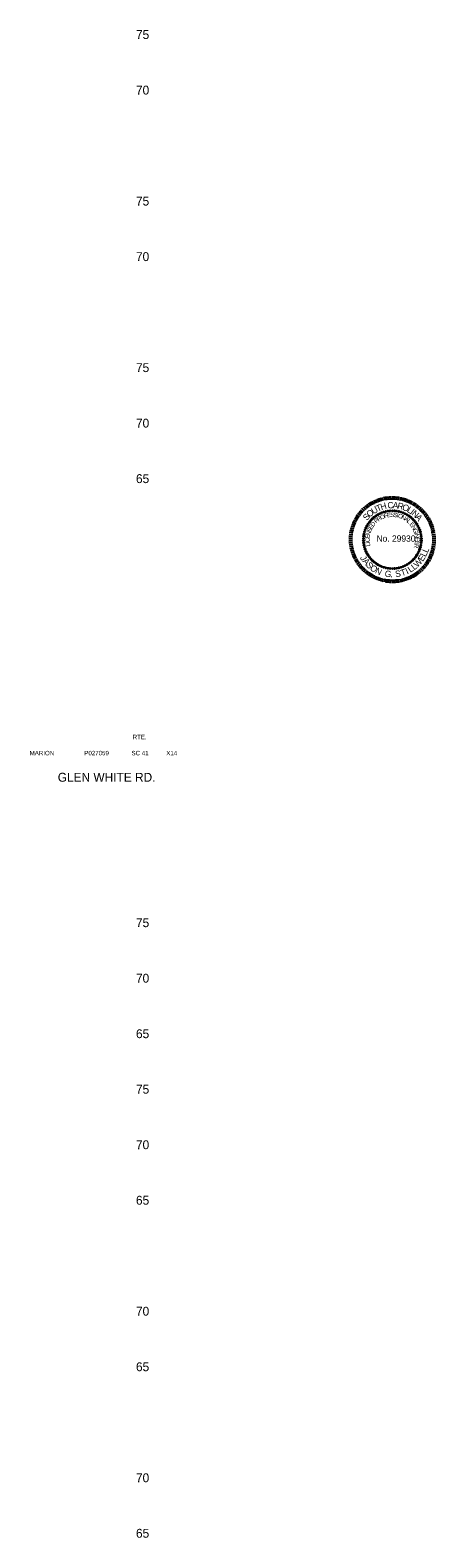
# Model space of a CAD drawing. Extents: x 1001 to 1184, y 1001 to 1562.
# Drawn here: x 1147.4 to 1183.9, y 1145 to 1280.8 of the extents above; entities that cross this region are included whole.
import ezdxf

# ---------------------------------------------------------------- set-up
doc = ezdxf.new("R2010")
doc.units = 0
for name, color, linetype in [('RD_HC_Cl', 7, 'Continuous'), ('RD_SHT_TX', 7, 'Continuous'), ('RD_TX_PEShield', 7, 'Continuous'), ('RD_XS_TX_Elev_EX', 7, 'Continuous')]:
    doc.layers.add(name, color=color, linetype=linetype)

# ---------------------------------------------------------------- blocks, each defined once
blk = doc.blocks.new('STILLWELL')
at = {"layer": 'RD_TX_PEShield'}
for p, q in [((-23.8, 25.9), (-26, 28.4)), ((-22.5, 27), (-24.5, 29.6)), ((-21.1, 28.1), (-23, 30.7)), ((-19.7, 29.1), (-21.5, 31.8)), ((-18.2, 30), (-19.9, 32.8)), ((-16.7, 30.8), (-18.2, 33.7)), ((-15.1, 31.6), (-16.5, 34.6)), ((-13.6, 32.3), (-14.8, 35.3)), ((-11.9, 32.9), (-13, 36)), ((-10.3, 33.4), (-11.2, 36.6)), ((-8.6, 33.9), (-9.4, 37.1)), ((-6.9, 34.3), (-7.5, 37.5)), ((-5.2, 34.6), (-5.7, 37.8)), ((-3.5, 34.8), (-3.8, 38)), ((-1.8, 34.9), (-1.9, 38.2)), ((0, 34.9), (0, 38.2)), ((1.7, 34.9), (1.9, 38.2)), ((3.4, 34.8), (3.7, 38)), ((5.2, 34.6), (5.6, 37.8)), ((6.9, 34.3), (7.5, 37.5)), ((8.6, 33.9), (9.3, 37.1)), ((10.2, 33.4), (11.2, 36.6)), ((11.9, 32.9), (13, 36)), ((13.5, 32.3), (14.7, 35.3)), ((15.1, 31.6), (16.5, 34.6)), ((16.6, 30.8), (18.2, 33.7)), ((18.2, 30), (19.8, 32.8)), ((19.6, 29.1), (21.4, 31.8)), ((21.1, 28.1), (23, 30.7)), ((22.4, 27), (24.5, 29.6)), ((23.8, 25.9), (25.9, 28.4)), ((-32.9, 13.4), (-35.9, 14.7)), ((-32.2, 15), (-35.1, 16.4)), ((-31.4, 16.5), (-34.2, 18.1)), ((-30.5, 18), (-33.3, 19.7)), ((-29.5, 19.4), (-32.2, 21.3)), ((-28.5, 20.9), (-31.1, 22.8)), ((-27.4, 22.2), (-29.9, 24.3)), ((-26.3, 23.5), (-28.7, 25.7)), ((-25.1, 24.7), (-27.4, 27.1)), ((25, 24.7), (27.3, 27.1)), ((26.2, 23.5), (28.6, 25.7)), ((27.4, 22.2), (29.9, 24.3)), ((28.5, 20.9), (31.1, 22.8)), ((29.5, 19.4), (32.2, 21.3)), ((30.4, 18), (33.2, 19.7)), ((31.3, 16.5), (34.2, 18.1)), ((32.1, 15), (35.1, 16.4)), ((32.9, 13.4), (35.9, 14.7)), ((-35.9, -0.1), (-39.2, 0)), ((-35.8, 1.7), (-39.1, 1.9)), ((-35.6, 3.4), (-38.9, 3.8)), ((-35.4, 5.1), (-38.6, 5.7)), ((-35.1, 6.8), (-38.2, 7.5)), ((-34.6, 8.5), (-37.8, 9.4)), ((-34.1, 10.2), (-37.2, 11.2)), ((-33.6, 11.8), (-36.6, 12.9)), ((33.5, 11.8), (36.6, 12.9)), ((34.1, 10.2), (37.2, 11.2)), ((34.6, 8.5), (37.7, 9.4)), ((35, 6.8), (38.2, 7.5)), ((35.3, 5.1), (38.5, 5.7)), ((35.6, 3.4), (38.8, 3.8)), ((35.7, 1.7), (39, 1.9)), ((35.8, -0.1), (39.1, 0)), ((-35.9, -1.8), (-39.2, -1.9)), ((-35.8, -3.5), (-39.1, -3.8)), ((-35.6, -5.3), (-38.9, -5.6)), ((-35.4, -7), (-38.6, -7.5)), ((-35.1, -8.7), (-38.2, -9.4)), ((-34.6, -10.4), (-37.8, -11.2)), ((-34.1, -12), (-37.2, -13)), ((34.1, -12), (37.2, -13)), ((34.6, -10.4), (37.7, -11.2)), ((35, -8.7), (38.2, -9.4)), ((35.3, -7), (38.5, -7.5)), ((35.6, -5.3), (38.8, -5.6)), ((35.7, -3.5), (39, -3.8)), ((35.8, -1.8), (39.1, -1.9)), ((-33.6, -13.6), (-36.6, -14.8)), ((-32.9, -15.3), (-35.9, -16.6)), ((-32.2, -16.8), (-35.1, -18.3)), ((-31.4, -18.4), (-34.2, -19.9)), ((-30.5, -19.9), (-33.3, -21.6)), ((-29.5, -21.3), (-32.2, -23.2)), ((-28.5, -22.7), (-31.1, -24.7)), ((-27.4, -24.1), (-29.9, -26.2)), ((-26.3, -25.4), (-28.7, -27.6)), ((-25.1, -26.6), (-27.4, -28.9)), ((25, -26.6), (27.3, -28.9)), ((26.2, -25.4), (28.6, -27.6)), ((27.4, -24.1), (29.9, -26.2)), ((28.5, -22.7), (31.1, -24.7)), ((29.5, -21.3), (32.2, -23.2)), ((30.4, -19.9), (33.2, -21.6)), ((31.3, -18.4), (34.2, -19.9)), ((32.1, -16.8), (35.1, -18.3)), ((32.9, -15.3), (35.9, -16.6)), ((33.5, -13.6), (36.6, -14.8)), ((-23.8, -27.8), (-26, -30.2)), ((-22.5, -28.9), (-24.5, -31.4)), ((-21.1, -29.9), (-23, -32.6)), ((-19.7, -30.9), (-21.5, -33.7)), ((-18.2, -31.8), (-19.9, -34.7)), ((-16.7, -32.7), (-18.2, -35.6)), ((-15.1, -33.5), (-16.5, -36.4)), ((-13.6, -34.1), (-14.8, -37.2)), ((-11.9, -34.8), (-13, -37.8)), ((-10.3, -35.3), (-11.2, -38.4)), ((-8.6, -35.8), (-9.4, -38.9)), ((-6.9, -36.1), (-7.5, -39.3)), ((-5.2, -36.4), (-5.7, -39.7)), ((-3.5, -36.6), (-3.8, -39.9)), ((-1.8, -36.8), (-1.9, -40)), ((0, -36.8), (0, -40.1)), ((1.7, -36.8), (1.9, -40)), ((3.4, -36.6), (3.7, -39.9)), ((5.2, -36.4), (5.6, -39.7)), ((6.9, -36.1), (7.5, -39.3)), ((8.6, -35.8), (9.3, -38.9)), ((10.2, -35.3), (11.2, -38.4)), ((11.9, -34.8), (13, -37.8)), ((13.5, -34.1), (14.7, -37.2)), ((15.1, -33.5), (16.5, -36.4)), ((16.6, -32.7), (18.2, -35.6)), ((18.2, -31.8), (19.8, -34.7)), ((19.6, -30.9), (21.4, -33.7)), ((21.1, -29.9), (23, -32.6)), ((22.4, -28.9), (24.5, -31.4)), ((23.8, -27.8), (25.9, -30.2))]:
    blk.add_line(p, q, dxfattribs=at)
for centre in [(-21.9, 13.2), (-20.7, 14.9), (-19.5, 16.4), (-18.1, 17.8), (-16.6, 19.2), (-15, 20.4), (-13.3, 21.5), (-11.6, 22.4), (-9.8, 23.2), (-7.9, 23.9), (-6, 24.4), (-4, 24.8), (-2, 25), (0, 25.1), (2, 25), (3.9, 24.8), (5.9, 24.4), (7.8, 23.9), (9.7, 23.2), (11.5, 22.4), (13.3, 21.5), (15, 20.4), (16.5, 19.2), (18, 17.8), (19.4, 16.4), (20.7, 14.9), (21.8, 13.2), (-26.1, 0.1), (-25.9, 2.1), (-25.6, 4), (-25.1, 6), (-24.5, 7.9), (-23.8, 9.7), (-22.9, 11.5), (22.9, 11.5), (23.7, 9.7), (24.5, 7.9), (25.1, 6), (25.5, 4), (25.8, 2.1), (26, 0.1), (-26.1, -1.9), (-25.9, -3.9), (-25.6, -5.9), (-25.1, -7.8), (-24.5, -9.7), (-23.8, -11.6), (-22.9, -13.4), (22.9, -13.4), (23.7, -11.6), (24.5, -9.7), (25.1, -7.8), (25.5, -5.9), (25.8, -3.9), (26, -1.9), (-21.9, -15.1), (-20.7, -16.7), (-19.5, -18.3), (-18.1, -19.7), (-16.6, -21), (-15, -22.2), (-13.3, -23.3), (-11.6, -24.3), (-9.8, -25.1), (-7.9, -25.8), (-6, -26.3), (-4, -26.7), (-2, -26.9), (0, -27), (2, -26.9), (3.9, -26.7), (5.9, -26.3), (7.8, -25.8), (9.7, -25.1), (11.5, -24.3), (13.3, -23.3), (15, -22.2), (16.5, -21), (18, -19.7), (19.4, -18.3), (20.7, -16.7), (21.8, -15.1)]:
    blk.add_circle(centre, 0.49, dxfattribs=at)
for s, height, rotation, p in [('U', 5.68, 32.2152, (-16.9, 21.8)), ('T', 5.68, 23.5044, (-13.2, 24.1)), ('H', 5.68, 16.1357, (-9.9, 25.6)), ('C', 5.68, 4.076, (-4.2, 27.1)), ('A', 5.68, 355.3651, (0.1, 27.4)), ('R', 5.68, 347.3188, (4.1, 27.1)), ('O', 5.68, 338.6079, (8.3, 26.2)), ('L', 5.68, 329.226, (12.6, 24.4)), ('S', 5.68, 49.6435, (-22.9, 15.8)), ('O', 5.68, 41.5972, (-20.4, 18.8)), ('D', 3.92, 52.5376, (-17.1, 10.3)), ('P', 3.92, 41.0022, (-14.5, 13.5)), ('R', 3.92, 33.3057, (-12.5, 15.3)), ('O', 3.92, 24.9735, (-10, 16.9)), ('F', 3.92, 15.9995, (-7.1, 18.3)), ('E', 3.92, 8.9511, (-4.7, 19)), ('S', 3.92, 1.2546, (-1.9, 19.4)), ('S', 3.92, 353.558, (0.8, 19.5)), ('I', 3.92, 345.8615, (3.5, 19.2)), ('O', 3.92, 342.6583, (4.7, 19)), ('N', 3.92, 333.6842, (7.7, 18)), ('A', 3.92, 325.3521, (10.4, 16.7)), ('L', 3.92, 317.6555, (12.6, 15.1)), ('E', 3.92, 308.0396, (15.1, 12.8)), ('I', 5.68, 322.5218, (15.5, 22.8)), ('N', 5.68, 319.1729, (16.8, 21.8)), ('A', 5.68, 310.4621, (20.1, 19)), ('C', 3.92, 92.2915, (-20.4, -3.2)), ('E', 3.92, 83.9594, (-20.5, -0.2)), ('N', 3.92, 76.2628, (-20.2, 2.5)), ('S', 3.92, 67.9307, (-19.5, 5.4)), ('E', 3.92, 60.2341, (-18.5, 7.9)), ('N', 3.92, 300.343, (16.8, 10.6)), ('G', 3.92, 292.0109, (18.3, 8.1)), ('I', 3.92, 283.0368, (19.5, 5.1)), ('N', 3.92, 279.8336, (19.8, 4)), ('E', 3.92, 271.5014, (20.3, 1.1)), ('I', 3.92, 95.4947, (-20.2, -4.3)), ('L', 3.92, 101.9075, (-19.7, -6.6)), ('R', 3.92, 256.1083, (20.1, -4.4)), ('E', 3.92, 263.8049, (20.4, -1.7)), ('L', 5.68, 65.098, (30, -16.9)), ('L', 5.68, 65.098, (31.6, -13.3)), ('J', 5.68, 299.033, (-29.4, -17.3)), ('A', 5.68, 310.5887, (-27.2, -20.6)), ('S', 5.68, 310.5887, (-24.3, -24)), ('O', 5.68, 321.0072, (-20.8, -27.4)), ('N', 5.68, 333.4326, (-16, -30.8)), ('T', 5.68, 18.9019, (8.5, -33.9)), ('I', 5.68, 25.3991, (13.3, -32.2)), ('L', 5.68, 34.0644, (16.2, -30.9)), ('L', 5.68, 37.6708, (19.6, -28.7)), ('W', 5.68, 47.0518, (22.6, -26.4)), ('E', 5.68, 56.4327, (27.3, -21.1)), ('G', 5.68, 352.2045, (-7.2, -34.2)), ('.', 5.68, 0.8698, (-1.8, -34.9)), ('S', 5.68, 8.0826, (2.9, -34.8))]:
    blk.add_text(s, height=height, rotation=rotation, dxfattribs=at).set_placement(p)
blk.add_text('No. 29930', height=5.68, dxfattribs=at).set_placement((-14.3, -2.8))

msp = doc.modelspace()

# ---------------------------------------------------------------- block references
at = {"layer": 'RD_HC_Cl', "xscale": 0.1, "yscale": 0.10000000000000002}
msp.add_blockref('STILLWELL', (1180, 1235), dxfattribs=at)

# ---------------------------------------------------------------- texts
at = {"layer": 'RD_SHT_TX'}
for s, height, p in [('RTE.', 0.4, (1156.62, 1216.93)), ('MARION', 0.4, (1147.35, 1215.48)), ('P027059', 0.4, (1152.27, 1215.48)), ('SC 41', 0.4, (1156.52, 1215.48)), ('X14', 0.4, (1159.65, 1215.48)), ('GLEN WHITE RD.', 0.8, (1149.88, 1213.1))]:
    msp.add_text(s, height=height, dxfattribs=at).set_placement(p)
at = {"layer": 'RD_XS_TX_Elev_EX'}
for s, p in [('75', (1156.92, 1280)), ('70', (1156.92, 1275)), ('75', (1156.92, 1265)), ('70', (1156.92, 1260)), ('75', (1156.92, 1250)), ('70', (1156.92, 1245)), ('65', (1156.92, 1240)), ('75', (1156.92, 1200)), ('70', (1156.92, 1195)), ('65', (1156.92, 1190)), ('75', (1156.92, 1185)), ('70', (1156.92, 1180)), ('65', (1156.92, 1175)), ('70', (1156.92, 1165)), ('65', (1156.92, 1160)), ('70', (1156.92, 1150)), ('65', (1156.92, 1145))]:
    msp.add_text(s, height=0.8, dxfattribs=at).set_placement(p)

doc.saveas('drawing.dxf')
